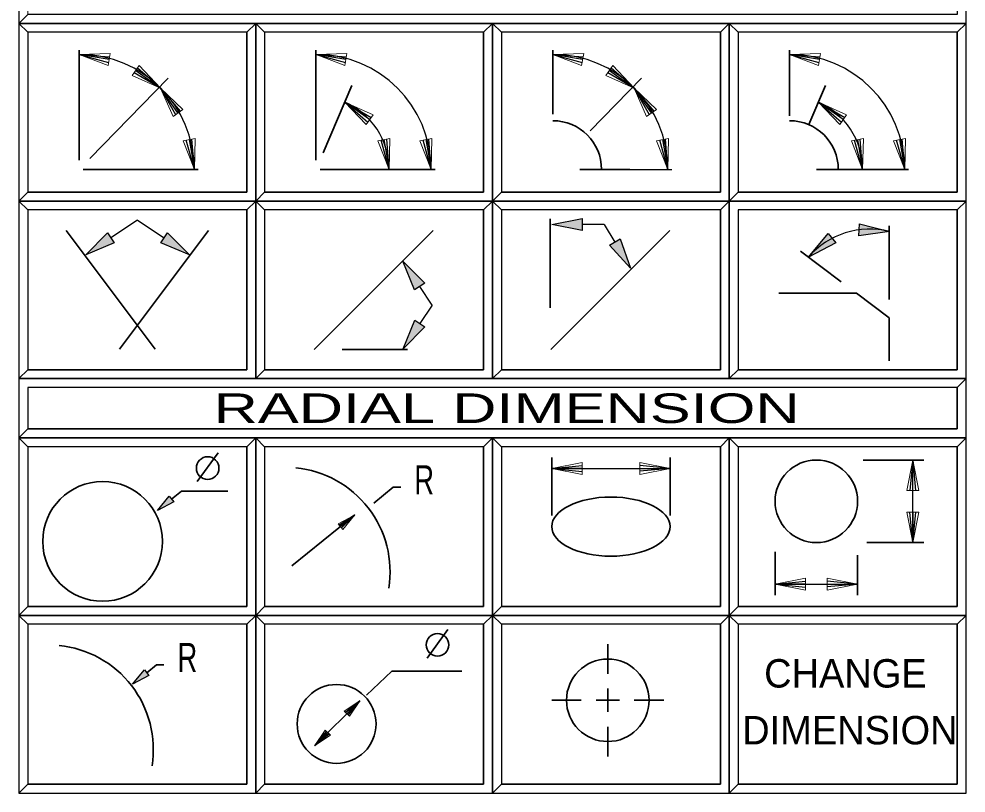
# Model space of a CAD drawing. Extents: x 95906.9 to 95918.9, y 90964.8 to 90972.9.
# Drawn here: x 95908.932 to 95910.532, y 90970.062 to 90971.369 of the extents above; entities that cross this region are included whole.
import ezdxf
from ezdxf.enums import TextEntityAlignment as Align

# ---------------------------------------------------------------- set-up
doc = ezdxf.new("R2010")
doc.units = 0
doc.header["$LTSCALE"] = 0.019
for name, color, linetype, lineweight in [('1', 7, 'Continuous', 25), ('11', 7, 'Continuous', 25), ('12', 7, 'Continuous', 25), ('17', 7, 'Continuous', 25), ('2', 7, 'Continuous', 13), ('3', 7, 'Continuous', 25), ('4', 7, 'Continuous', 35), ('6', 7, 'Continuous', 35), ('7', 7, 'Continuous', 35)]:
    doc.layers.add(name, color=color, linetype=linetype, lineweight=lineweight)

msp = doc.modelspace()

# ---------------------------------------------------------------- hatches: boundary and pattern name
at = {"layer": '6'}
for points in [[(95909.8327, 90971.0222), (95909.8839, 90971.0324), (95909.8839, 90971.012)], [(95910.3522, 90971.0231), (95910.4029, 90971.0104), (95910.3513, 90971.0026)], [(95909.0451, 90970.971), (95909.082, 90971.0079), (95909.0934, 90970.9909)], [(95909.1719, 90970.9909), (95909.1833, 90971.0079), (95909.2202, 90970.971)], [(95909.9477, 90970.9976), (95909.9655, 90970.9485), (95909.9302, 90970.9869)], [(95910.2659, 90970.9669), (95910.2995, 90971.0068), (95910.3123, 90970.9909)], [(95909.6178, 90970.9232), (95909.6008, 90970.9118), (95909.5809, 90970.9601)], [(95909.6182, 90970.849), (95909.5813, 90970.8121), (95909.6012, 90970.8604)], [(95909.1661, 90970.539), (95909.1861, 90970.5631), (95909.1938, 90970.5535)], [(95909.1242, 90970.2457), (95909.1442, 90970.2698), (95909.1519, 90970.2602)]]:
    msp.add_hatch(color=256, dxfattribs=at).paths.add_polyline_path(points)

# ---------------------------------------------------------------- linework, layer by layer
at = {"layer": '1'}
for points in [[(95908.9323, 90971.3617), (95910.5323, 90971.3617), (95910.5323, 90971.4617), (95908.9323, 90971.4617)], [(95908.9323, 90971.0617), (95909.3323, 90971.0617), (95909.3323, 90971.3617), (95908.9323, 90971.3617)], [(95909.3323, 90971.0617), (95909.7323, 90971.0617), (95909.7323, 90971.3617), (95909.3323, 90971.3617)], [(95909.7323, 90971.0617), (95910.1323, 90971.0617), (95910.1323, 90971.3617), (95909.7323, 90971.3617)], [(95910.1323, 90971.0617), (95910.5323, 90971.0617), (95910.5323, 90971.3617), (95910.1323, 90971.3617)], [(95908.9323, 90970.7617), (95909.3323, 90970.7617), (95909.3323, 90971.0617), (95908.9323, 90971.0617)], [(95909.3323, 90970.7617), (95909.7323, 90970.7617), (95909.7323, 90971.0617), (95909.3323, 90971.0617)], [(95909.7323, 90970.7617), (95910.1323, 90970.7617), (95910.1323, 90971.0617), (95909.7323, 90971.0617)], [(95910.1323, 90970.7617), (95910.5323, 90970.7617), (95910.5323, 90971.0617), (95910.1323, 90971.0617)], [(95908.9323, 90970.6617), (95910.5323, 90970.6617), (95910.5323, 90970.7617), (95908.9323, 90970.7617)], [(95908.9323, 90970.3617), (95909.3323, 90970.3617), (95909.3323, 90970.6617), (95908.9323, 90970.6617)], [(95909.3323, 90970.3617), (95909.7323, 90970.3617), (95909.7323, 90970.6617), (95909.3323, 90970.6617)], [(95909.7323, 90970.3617), (95910.1323, 90970.3617), (95910.1323, 90970.6617), (95909.7323, 90970.6617)], [(95910.1323, 90970.3617), (95910.5323, 90970.3617), (95910.5323, 90970.6617), (95910.1323, 90970.6617)], [(95908.9323, 90970.0617), (95909.3323, 90970.0617), (95909.3323, 90970.3617), (95908.9323, 90970.3617)], [(95909.3323, 90970.0617), (95909.7323, 90970.0617), (95909.7323, 90970.3617), (95909.3323, 90970.3617)], [(95909.7323, 90970.0617), (95910.1323, 90970.0617), (95910.1323, 90970.3617), (95909.7323, 90970.3617)], [(95910.1323, 90970.0617), (95910.5323, 90970.0617), (95910.5323, 90970.3617), (95910.1323, 90970.3617)]]:
    msp.add_lwpolyline(points, close=True, dxfattribs=at)
at = {"layer": '11'}
for points in [[(95908.9473, 90971.0767), (95909.3173, 90971.0767), (95909.3173, 90971.3467), (95908.9473, 90971.3467)], [(95909.3473, 90971.0767), (95909.7173, 90971.0767), (95909.7173, 90971.3467), (95909.3473, 90971.3467)], [(95909.7473, 90971.0767), (95910.1173, 90971.0767), (95910.1173, 90971.3467), (95909.7473, 90971.3467)], [(95910.1473, 90971.0767), (95910.5173, 90971.0767), (95910.5173, 90971.3467), (95910.1473, 90971.3467)], [(95908.9473, 90970.7767), (95909.3173, 90970.7767), (95909.3173, 90971.0467), (95908.9473, 90971.0467)], [(95909.3473, 90970.7767), (95909.7173, 90970.7767), (95909.7173, 90971.0467), (95909.3473, 90971.0467)], [(95909.7473, 90970.7767), (95910.1173, 90970.7767), (95910.1173, 90971.0467), (95909.7473, 90971.0467)], [(95910.1473, 90970.7767), (95910.5173, 90970.7767), (95910.5173, 90971.0467), (95910.1473, 90971.0467)], [(95908.9473, 90970.3767), (95909.3173, 90970.3767), (95909.3173, 90970.6467), (95908.9473, 90970.6467)], [(95909.3473, 90970.3767), (95909.7173, 90970.3767), (95909.7173, 90970.6467), (95909.3473, 90970.6467)], [(95909.7473, 90970.3767), (95910.1173, 90970.3767), (95910.1173, 90970.6467), (95909.7473, 90970.6467)], [(95910.1473, 90970.3767), (95910.5173, 90970.3767), (95910.5173, 90970.6467), (95910.1473, 90970.6467)], [(95908.9473, 90970.0767), (95909.3173, 90970.0767), (95909.3173, 90970.3467), (95908.9473, 90970.3467)], [(95909.3473, 90970.0767), (95909.7173, 90970.0767), (95909.7173, 90970.3467), (95909.3473, 90970.3467)], [(95909.7473, 90970.0767), (95910.1173, 90970.0767), (95910.1173, 90970.3467), (95909.7473, 90970.3467)], [(95910.1473, 90970.0767), (95910.5173, 90970.0767), (95910.5173, 90970.3467), (95910.1473, 90970.3467)]]:
    msp.add_lwpolyline(points, close=True, dxfattribs=at)
at = {"layer": '12'}
for points in [[(95908.9473, 90971.0767), (95909.3173, 90971.0767), (95909.3173, 90971.3467), (95908.9473, 90971.3467)], [(95908.9473, 90970.3767), (95909.3173, 90970.3767), (95909.3173, 90970.6467), (95908.9473, 90970.6467)]]:
    msp.add_lwpolyline(points, close=True, dxfattribs=at)
at = {"layer": '17'}
msp.add_lwpolyline([(95908.9473, 90970.6767), (95910.5173, 90970.6767), (95910.5173, 90970.7467), (95908.9473, 90970.7467)], close=True, dxfattribs=at)
at = {"layer": '2'}
for points in [[(95908.9323, 90971.4617), (95908.9323, 90971.3617), (95908.9473, 90971.3767), (95908.9473, 90971.4467), (95910.5173, 90971.4467), (95910.5323, 90971.4617)], [(95908.9323, 90971.3617), (95908.9323, 90971.0617), (95908.9473, 90971.0767), (95908.9473, 90971.3467), (95909.3173, 90971.3467), (95909.3323, 90971.3617)], [(95909.3323, 90971.3617), (95909.3323, 90971.0617), (95909.3473, 90971.0767), (95909.3473, 90971.3467), (95909.7173, 90971.3467), (95909.7323, 90971.3617)], [(95909.7323, 90971.3617), (95909.7323, 90971.0617), (95909.7473, 90971.0767), (95909.7473, 90971.3467), (95910.1173, 90971.3467), (95910.1323, 90971.3617)], [(95910.1323, 90971.3617), (95910.1323, 90971.0617), (95910.1473, 90971.0767), (95910.1473, 90971.3467), (95910.5173, 90971.3467), (95910.5323, 90971.3617)], [(95908.9323, 90971.0617), (95908.9323, 90970.7617), (95908.9473, 90970.7767), (95908.9473, 90971.0467), (95909.3173, 90971.0467), (95909.3323, 90971.0617)], [(95909.3323, 90971.0617), (95909.3323, 90970.7617), (95909.3473, 90970.7767), (95909.3473, 90971.0467), (95909.7173, 90971.0467), (95909.7323, 90971.0617)], [(95909.7323, 90971.0617), (95909.7323, 90970.7617), (95909.7473, 90970.7767), (95909.7473, 90971.0467), (95910.1173, 90971.0467), (95910.1323, 90971.0617)], [(95910.1323, 90971.0617), (95910.1323, 90970.7617), (95910.1473, 90970.7767), (95910.1473, 90971.0467), (95910.5173, 90971.0467), (95910.5323, 90971.0617)], [(95908.9323, 90970.7617), (95908.9323, 90970.6617), (95908.9473, 90970.6767), (95908.9473, 90970.7467), (95910.5173, 90970.7467), (95910.5323, 90970.7617)], [(95908.9323, 90970.6617), (95908.9323, 90970.3617), (95908.9473, 90970.3767), (95908.9473, 90970.6467), (95909.3173, 90970.6467), (95909.3323, 90970.6617)], [(95909.3323, 90970.6617), (95909.3323, 90970.3617), (95909.3473, 90970.3767), (95909.3473, 90970.6467), (95909.7173, 90970.6467), (95909.7323, 90970.6617)], [(95909.7323, 90970.6617), (95909.7323, 90970.3617), (95909.7473, 90970.3767), (95909.7473, 90970.6467), (95910.1173, 90970.6467), (95910.1323, 90970.6617)], [(95910.1323, 90970.6617), (95910.1323, 90970.3617), (95910.1473, 90970.3767), (95910.1473, 90970.6467), (95910.5173, 90970.6467), (95910.5323, 90970.6617)], [(95908.9323, 90970.3617), (95908.9323, 90970.0617), (95908.9473, 90970.0767), (95908.9473, 90970.3467), (95909.3173, 90970.3467), (95909.3323, 90970.3617)], [(95909.3323, 90970.3617), (95909.3323, 90970.0617), (95909.3473, 90970.0767), (95909.3473, 90970.3467), (95909.7173, 90970.3467), (95909.7323, 90970.3617)], [(95909.7323, 90970.3617), (95909.7323, 90970.0617), (95909.7473, 90970.0767), (95909.7473, 90970.3467), (95910.1173, 90970.3467), (95910.1323, 90970.3617)], [(95910.1323, 90970.3617), (95910.1323, 90970.0617), (95910.1473, 90970.0767), (95910.1473, 90970.3467), (95910.5173, 90970.3467), (95910.5323, 90970.3617)]]:
    msp.add_lwpolyline(points, close=True, dxfattribs=at)
at = {"layer": '3'}
for points in [[(95908.9323, 90971.3617), (95910.5323, 90971.3617), (95910.5323, 90971.4617), (95910.5173, 90971.4467), (95910.5173, 90971.3767), (95908.9473, 90971.3767)], [(95908.9323, 90971.0617), (95909.3323, 90971.0617), (95909.3323, 90971.3617), (95909.3173, 90971.3467), (95909.3173, 90971.0767), (95908.9473, 90971.0767)], [(95909.3323, 90971.0617), (95909.7323, 90971.0617), (95909.7323, 90971.3617), (95909.7173, 90971.3467), (95909.7173, 90971.0767), (95909.3473, 90971.0767)], [(95909.7323, 90971.0617), (95910.1323, 90971.0617), (95910.1323, 90971.3617), (95910.1173, 90971.3467), (95910.1173, 90971.0767), (95909.7473, 90971.0767)], [(95910.1323, 90971.0617), (95910.5323, 90971.0617), (95910.5323, 90971.3617), (95910.5173, 90971.3467), (95910.5173, 90971.0767), (95910.1473, 90971.0767)], [(95908.9323, 90970.7617), (95909.3323, 90970.7617), (95909.3323, 90971.0617), (95909.3173, 90971.0467), (95909.3173, 90970.7767), (95908.9473, 90970.7767)], [(95909.3323, 90970.7617), (95909.7323, 90970.7617), (95909.7323, 90971.0617), (95909.7173, 90971.0467), (95909.7173, 90970.7767), (95909.3473, 90970.7767)], [(95909.7323, 90970.7617), (95910.1323, 90970.7617), (95910.1323, 90971.0617), (95910.1173, 90971.0467), (95910.1173, 90970.7767), (95909.7473, 90970.7767)], [(95910.1323, 90970.7617), (95910.5323, 90970.7617), (95910.5323, 90971.0617), (95910.5173, 90971.0467), (95910.5173, 90970.7767), (95910.1473, 90970.7767)], [(95908.9323, 90970.6617), (95910.5323, 90970.6617), (95910.5323, 90970.7617), (95910.5173, 90970.7467), (95910.5173, 90970.6767), (95908.9473, 90970.6767)], [(95908.9323, 90970.3617), (95909.3323, 90970.3617), (95909.3323, 90970.6617), (95909.3173, 90970.6467), (95909.3173, 90970.3767), (95908.9473, 90970.3767)], [(95909.3323, 90970.3617), (95909.7323, 90970.3617), (95909.7323, 90970.6617), (95909.7173, 90970.6467), (95909.7173, 90970.3767), (95909.3473, 90970.3767)], [(95909.7323, 90970.3617), (95910.1323, 90970.3617), (95910.1323, 90970.6617), (95910.1173, 90970.6467), (95910.1173, 90970.3767), (95909.7473, 90970.3767)], [(95910.1323, 90970.3617), (95910.5323, 90970.3617), (95910.5323, 90970.6617), (95910.5173, 90970.6467), (95910.5173, 90970.3767), (95910.1473, 90970.3767)], [(95908.9323, 90970.0617), (95909.3323, 90970.0617), (95909.3323, 90970.3617), (95909.3173, 90970.3467), (95909.3173, 90970.0767), (95908.9473, 90970.0767)], [(95909.3323, 90970.0617), (95909.7323, 90970.0617), (95909.7323, 90970.3617), (95909.7173, 90970.3467), (95909.7173, 90970.0767), (95909.3473, 90970.0767)], [(95909.7323, 90970.0617), (95910.1323, 90970.0617), (95910.1323, 90970.3617), (95910.1173, 90970.3467), (95910.1173, 90970.0767), (95909.7473, 90970.0767)], [(95910.1323, 90970.0617), (95910.5323, 90970.0617), (95910.5323, 90970.3617), (95910.5173, 90970.3467), (95910.5173, 90970.0767), (95910.1473, 90970.0767)]]:
    msp.add_lwpolyline(points, close=True, dxfattribs=at)
at = {"layer": '4'}
for p, q in [((95908.9473, 90971.3467), (95908.9323, 90971.3617)), ((95909.3473, 90971.3467), (95909.3323, 90971.3617)), ((95909.7473, 90971.3467), (95909.7323, 90971.3617)), ((95910.1473, 90971.3467), (95910.1323, 90971.3617)), ((95908.9473, 90971.0467), (95908.9323, 90971.0617)), ((95909.3473, 90971.0467), (95909.3323, 90971.0617)), ((95909.7473, 90971.0467), (95909.7323, 90971.0617)), ((95908.9473, 90970.6467), (95908.9323, 90970.6617)), ((95908.9473, 90970.6467), (95908.9323, 90970.6617)), ((95909.3473, 90970.6467), (95909.3323, 90970.6617)), ((95909.7473, 90970.6467), (95909.7323, 90970.6617)), ((95910.1473, 90970.6467), (95910.1323, 90970.6617)), ((95908.9473, 90970.3467), (95908.9323, 90970.3617)), ((95909.3473, 90970.3467), (95909.3323, 90970.3617)), ((95909.7473, 90970.3467), (95909.7323, 90970.3617)), ((95910.1473, 90970.3467), (95910.1323, 90970.3617))]:
    msp.add_line(p, q, dxfattribs=at)
at = {"layer": '6'}
for p, q in [((95909.0341, 90971.1304), (95909.0341, 90971.3162)), ((95909.4341, 90971.1304), (95909.4341, 90971.3162)), ((95909.8341, 90971.2083), (95909.8341, 90971.3162)), ((95910.2341, 90971.2054), (95910.2341, 90971.3162)), ((95909.0523, 90971.1335), (95909.1842, 90971.2693)), ((95909.8975, 90971.1801), (95909.9842, 90971.2693)), ((95909.4462, 90971.1433), (95909.4949, 90971.2567)), ((95910.2666, 90971.1908), (95910.2949, 90971.2567)), ((95909.0409, 90971.1149), (95909.2353, 90971.1149)), ((95909.4409, 90971.1149), (95909.6353, 90971.1149)), ((95909.8798, 90971.1149), (95909.9643, 90971.1149)), ((95910.2798, 90971.1149), (95910.3643, 90971.1149)), ((95910.327, 90971.1149), (95910.4353, 90971.1149)), ((95909.8295, 90970.8815), (95909.8295, 90971.0315)), ((95909.1623, 90970.8117), (95909.0123, 90971.0117)), ((95909.1023, 90970.8117), (95909.2523, 90971.0117)), ((95909.4309, 90970.8109), (95909.6321, 90971.0121)), ((95909.8309, 90970.8109), (95910.0321, 90971.0121)), ((95910.4024, 90970.8951), (95910.4024, 90971.0197)), ((95910.2527, 90970.9769), (95910.3212, 90970.9254)), ((95910.2159, 90970.9059), (95910.3471, 90970.9059)), ((95910.3471, 90970.9059), (95910.4024, 90970.8643)), ((95910.4024, 90970.792), (95910.4024, 90970.8643)), ((95909.4785, 90970.8109), (95909.5886, 90970.8109)), ((95909.2335, 90970.5879), (95909.2688, 90970.6366)), ((95909.8323, 90970.5305), (95909.8323, 90970.6287)), ((95910.0323, 90970.5305), (95910.0323, 90970.6287)), ((95910.3587, 90970.6242), (95910.4611, 90970.6242)), ((95909.2067, 90970.5718), (95909.1899, 90970.5583)), ((95909.2067, 90970.5718), (95909.2853, 90970.5718)), ((95909.3933, 90970.4455), (95909.4992, 90970.5312)), ((95909.4992, 90970.5312), (95909.4771, 90970.5097)), ((95910.3644, 90970.4848), (95910.4611, 90970.4848)), ((95910.2097, 90970.4694), (95910.2097, 90970.3958)), ((95910.3491, 90970.4636), (95910.3491, 90970.3958)), ((95909.6218, 90970.2893), (95909.6571, 90970.338)), ((95909.927, 90970.3131), (95909.927, 90970.2631)), ((95909.927, 90970.2381), (95909.927, 90970.1987)), ((95909.4324, 90970.1419), (95909.5079, 90970.2174)), ((95909.5079, 90970.2174), (95909.4882, 90970.1937)), ((95909.8323, 90970.2184), (95909.8823, 90970.2184)), ((95909.9073, 90970.2184), (95909.9467, 90970.2184)), ((95910.0217, 90970.2184), (95909.9717, 90970.2184)), ((95909.4324, 90970.1419), (95909.4521, 90970.1656)), ((95909.927, 90970.1237), (95909.927, 90970.1737))]:
    msp.add_line(p, q, dxfattribs=at)
at = {"layer": '6', "lineweight": 25}
for p, q in [((95909.0342, 90971.3094), (95909.0854, 90971.3052)), ((95909.4342, 90971.3094), (95909.4854, 90971.3052)), ((95909.8342, 90971.3094), (95909.8854, 90971.3052)), ((95910.2342, 90971.3094), (95910.2854, 90971.3052)), ((95909.1716, 90971.2525), (95909.1269, 90971.278)), ((95909.9716, 90971.2525), (95909.9269, 90971.278)), ((95909.1716, 90971.2525), (95909.2049, 90971.2133)), ((95909.9716, 90971.2525), (95910.0049, 90971.2133)), ((95909.4828, 90971.2285), (95909.5275, 90971.203)), ((95910.2828, 90971.2285), (95910.3275, 90971.203)), ((95909.2286, 90971.115), (95909.215, 90971.1646)), ((95909.5576, 90971.115), (95909.544, 90971.1646)), ((95909.6286, 90971.115), (95909.615, 90971.1646)), ((95910.0286, 90971.115), (95910.015, 90971.1646)), ((95910.3576, 90971.115), (95910.344, 90971.1646)), ((95910.4286, 90971.115), (95910.415, 90971.1646)), ((95909.0798, 90971.1149), (95909.1643, 90971.1149)), ((95909.0798, 90971.1149), (95909.1643, 90971.1149)), ((95909.4798, 90971.1149), (95909.5643, 90971.1149)), ((95909.4798, 90971.1149), (95909.5643, 90971.1149)), ((95909.9284, 90971.1149), (95910.0353, 90971.1149)), ((95909.1327, 90971.0294), (95909.0877, 90970.9994)), ((95909.1327, 90971.0294), (95909.1776, 90970.9994)), ((95909.9208, 90971.0222), (95909.8839, 90971.0222)), ((95909.9208, 90971.022), (95909.9389, 90970.9922)), ((95909.6305, 90970.8856), (95909.6093, 90970.9175)), ((95909.6303, 90970.8855), (95909.6097, 90970.8547)), ((95910.4423, 90970.4848), (95910.4423, 90970.6242)), ((95910.4423, 90970.6242), (95910.4471, 90970.573)), ((95909.8323, 90970.6099), (95909.8835, 90970.6147)), ((95909.8323, 90970.6099), (95910.0323, 90970.6099)), ((95910.0323, 90970.6099), (95909.9811, 90970.6051)), ((95910.4423, 90970.4848), (95910.4375, 90970.536)), ((95910.2097, 90970.4146), (95910.2609, 90970.4194)), ((95910.2097, 90970.4146), (95910.3491, 90970.4146)), ((95910.3491, 90970.4146), (95910.2979, 90970.4098))]:
    msp.add_line(p, q, dxfattribs=at)
at = {"layer": '6', "lineweight": 13}
for points in [[(95909.0828, 90971.2904), (95909.0342, 90971.3094), (95909.0864, 90971.3106)], [(95909.0828, 90971.2904), (95909.0342, 90971.3094), (95909.0864, 90971.3106)], [(95909.0828, 90971.2904), (95909.0342, 90971.3094), (95909.0864, 90971.3106)], [(95909.0828, 90971.2904), (95909.0342, 90971.3094), (95909.0864, 90971.3106)], [(95909.0828, 90971.2904), (95909.0342, 90971.3094), (95909.0864, 90971.3106)], [(95909.4828, 90971.2904), (95909.4342, 90971.3094), (95909.4864, 90971.3106)], [(95909.8828, 90971.2904), (95909.8342, 90971.3094), (95909.8864, 90971.3106)], [(95910.2828, 90971.2904), (95910.2342, 90971.3094), (95910.2864, 90971.3106)], [(95909.1716, 90971.2525), (95909.1238, 90971.2735), (95909.1355, 90971.2903)], [(95909.9716, 90971.2525), (95909.9238, 90971.2735), (95909.9355, 90971.2903)], [(95909.1926, 90971.2047), (95909.1716, 90971.2525), (95909.2094, 90971.2164)], [(95909.9926, 90971.2047), (95909.9716, 90971.2525), (95910.0094, 90971.2164)], [(95909.5189, 90971.1907), (95909.4828, 90971.2285), (95909.5306, 90971.2075)], [(95910.3189, 90971.1907), (95910.2828, 90971.2285), (95910.3306, 90971.2075)], [(95909.2286, 90971.115), (95909.2096, 90971.1636), (95909.2298, 90971.1672)], [(95909.5576, 90971.115), (95909.5386, 90971.1636), (95909.5588, 90971.1672)], [(95909.6286, 90971.115), (95909.6096, 90971.1636), (95909.6298, 90971.1672)], [(95910.0096, 90971.1636), (95910.0298, 90971.1672), (95910.0286, 90971.115)], [(95910.3588, 90971.1672), (95910.3576, 90971.115), (95910.3386, 90971.1636)], [(95910.4298, 90971.1672), (95910.4286, 90971.115), (95910.4096, 90971.1636)], [(95910.4321, 90970.573), (95910.4525, 90970.573), (95910.4423, 90970.6242)], [(95909.8835, 90970.6201), (95909.8835, 90970.5997), (95909.8323, 90970.6099)], [(95909.9811, 90970.5997), (95909.9811, 90970.6201), (95910.0323, 90970.6099)], [(95909.4792, 90970.5071), (95909.4715, 90970.5167), (95909.4992, 90970.5312)], [(95910.4525, 90970.536), (95910.4321, 90970.536), (95910.4423, 90970.4848)], [(95910.2609, 90970.4248), (95910.2609, 90970.4044), (95910.2097, 90970.4146)], [(95910.2979, 90970.4044), (95910.2979, 90970.4248), (95910.3491, 90970.4146)], [(95909.4905, 90970.1913), (95909.4818, 90970.2), (95909.5079, 90970.2174)], [(95909.4498, 90970.168), (95909.4585, 90970.1593), (95909.4324, 90970.1419)]]:
    msp.add_lwpolyline(points, close=True, dxfattribs=at)
at = {"layer": '6', "lineweight": 25}
for points in [[(95909.0846, 90971.3005), (95909.0342, 90971.3094), (95909.0838, 90971.2956)], [(95909.4846, 90971.3005), (95909.4342, 90971.3094), (95909.4838, 90971.2956)], [(95909.8846, 90971.3005), (95909.8342, 90971.3094), (95909.8838, 90971.2956)], [(95910.2846, 90971.3005), (95910.2342, 90971.3094), (95910.2838, 90971.2956)], [(95909.1297, 90971.2819), (95909.1716, 90971.2525), (95909.1325, 90971.286)], [(95909.9297, 90971.2819), (95909.9716, 90971.2525), (95909.9325, 90971.286)], [(95909.201, 90971.2106), (95909.1716, 90971.2525), (95909.1969, 90971.2077)], [(95910.001, 90971.2106), (95909.9716, 90971.2525), (95909.9969, 90971.2077)], [(95909.5247, 90971.1991), (95909.4828, 90971.2285), (95909.5219, 90971.195)], [(95910.3247, 90971.1991), (95910.2828, 90971.2285), (95910.3219, 90971.195)], [(95909.2197, 90971.1654), (95909.2286, 90971.115), (95909.2246, 90971.1663)], [(95909.5487, 90971.1654), (95909.5576, 90971.115), (95909.5536, 90971.1663)], [(95909.6197, 90971.1654), (95909.6286, 90971.115), (95909.6246, 90971.1663)], [(95910.0197, 90971.1654), (95910.0286, 90971.115), (95910.0246, 90971.1663)], [(95910.3487, 90971.1654), (95910.3576, 90971.115), (95910.3536, 90971.1663)], [(95910.4197, 90971.1654), (95910.4286, 90971.115), (95910.4246, 90971.1663)], [(95910.4423, 90970.573), (95910.4423, 90970.6242), (95910.4373, 90970.573)], [(95909.8835, 90970.6099), (95909.8323, 90970.6099), (95909.8835, 90970.6049)], [(95909.9811, 90970.6099), (95910.0323, 90970.6099), (95909.9811, 90970.6149)], [(95910.4423, 90970.536), (95910.4423, 90970.4848), (95910.4473, 90970.536)], [(95910.2979, 90970.4146), (95910.3491, 90970.4146), (95910.2979, 90970.4196)], [(95910.2609, 90970.4146), (95910.2097, 90970.4146), (95910.2609, 90970.4096)]]:
    msp.add_lwpolyline(points, dxfattribs=at)
for points in [[(95909.8327, 90971.0222), (95909.8839, 90971.0324), (95909.8839, 90971.012)], [(95910.3522, 90971.0231), (95910.4029, 90971.0104), (95910.3513, 90971.0026)], [(95909.0451, 90970.971), (95909.082, 90971.0079), (95909.0934, 90970.9909)], [(95909.1719, 90970.9909), (95909.1833, 90971.0079), (95909.2202, 90970.971)], [(95909.9477, 90970.9976), (95909.9655, 90970.9485), (95909.9302, 90970.9869)], [(95910.2659, 90970.9669), (95910.2995, 90971.0068), (95910.3123, 90970.9909)], [(95909.6178, 90970.9232), (95909.6008, 90970.9118), (95909.5809, 90970.9601)], [(95909.6182, 90970.849), (95909.5813, 90970.8121), (95909.6012, 90970.8604)], [(95909.1661, 90970.539), (95909.1861, 90970.5631), (95909.1938, 90970.5535)], [(95909.1242, 90970.2457), (95909.1442, 90970.2698), (95909.1519, 90970.2602)]]:
    msp.add_lwpolyline(points, close=True, dxfattribs=at)
at = {"layer": '6'}
for points in [[(95909.5319, 90970.5513), (95909.5647, 90970.5782), (95909.5773, 90970.5782)], [(95909.4753, 90970.5119), (95909.4992, 90970.5312), (95909.4734, 90970.5142)], [(95909.1482, 90970.2647), (95909.1647, 90970.2782), (95909.1773, 90970.2782)], [(95909.5193, 90970.2271), (95909.5621, 90970.2674), (95909.6806, 90970.2674)], [(95909.4862, 90970.1957), (95909.5079, 90970.2174), (95909.4841, 90970.1978)], [(95909.4541, 90970.1636), (95909.4324, 90970.1419), (95909.4562, 90970.1615)]]:
    msp.add_lwpolyline(points, dxfattribs=at)
for centre, radius in [((95909.2511, 90970.6106), 0.0191), ((95910.2794, 90970.5545), 0.0697), ((95909.0736, 90970.4867), 0.1011), ((95909.6394, 90970.312), 0.0191), ((95909.927, 90970.2184), 0.0697), ((95909.4689, 90970.1784), 0.0666)]:
    msp.add_circle(centre, radius, dxfattribs=at)
at = {"layer": '6', "lineweight": 25}
for centre, radius, start, end in [((95909.0342, 90971.115), 0.1944, 0, 90), ((95909.4342, 90971.115), 0.1944, 0, 90), ((95909.8342, 90971.115), 0.1944, 0, 90), ((95910.2342, 90971.115), 0.1944, 0, 90), ((95909.4342, 90971.115), 0.1234, 0, 66.8084), ((95910.2342, 90971.115), 0.1234, 0, 66.8084), ((95910.3701, 90970.8764), 0.138, 76.2348, 139.0005)]:
    msp.add_arc(centre, radius, start, end, dxfattribs=at)
at = {"layer": '6'}
for centre, radius, start, end in [((95909.8342, 90971.115), 0.0823, 0, 90), ((95910.2342, 90971.115), 0.0823, 0, 90), ((95909.3829, 90970.4354), 0.1764, 350.954, 84.4361), ((95908.9829, 90970.1354), 0.1764, 350.954, 84.4361)]:
    msp.add_arc(centre, radius, start, end, dxfattribs=at)
msp.add_ellipse((95909.9323, 90970.5117), major_axis=(-0.1, 0), ratio=0.5, dxfattribs=at)

# ---------------------------------------------------------------- texts
at = {"layer": '6', "width": 0.7}
for p in [(95909.6169, 90970.5662), (95909.2169, 90970.2662)]:
    msp.add_text('R', height=0.0491, dxfattribs=at).set_placement(p, align=Align.CENTER)
at = {"layer": '6'}
for s, p in [('CHANGE', (95910.3285, 90970.2399)), ('DIMENSION', (95910.336, 90970.1439))]:
    msp.add_text(s, height=0.048, dxfattribs=at).set_placement(p, align=Align.CENTER)
at = {"layer": '7', "width": 1.55}
msp.add_text('    RADIAL DIMENSION   ', height=0.04999, dxfattribs=at).set_placement((95909.7418, 90970.6867), align=Align.CENTER)

doc.saveas('drawing.dxf')
